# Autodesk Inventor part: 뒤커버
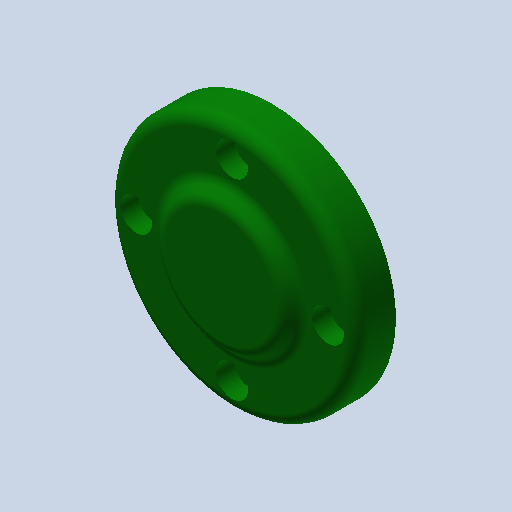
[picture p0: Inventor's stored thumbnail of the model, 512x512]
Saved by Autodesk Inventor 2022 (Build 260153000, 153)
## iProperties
Created: 2015-09
Part Number: 뒤커버
Material: 알루미늄 6061
Document SubType Name: Modeling
Designer: mduedu
Density: 1 g/cm^3
Appearance: 진녹색
Author: mduedu
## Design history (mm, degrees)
sketch "스케치1"
  geometry: L1 (0, 9)-(0, -9); L2 (0, 9)-(15, 9); L3 (15, 9)-(18, 6); L4 (18, 6)-(31, 6); L5 (31, 6)-(31, -4); L6 (31, -4)-(17.5, -4); L7 (17.5, -4)-(17.5, -9); L8 (17.5, -9)-(0, -9); 2 further points
  constraints: 16 end point, 3 parallel, 2 perpendicular, 1 coincident, 1 horizontal, 1 midpoint, 1 vertical
  dimensions: "d1" = 3 distance between parallel lines of L4 L2; "d2" = 10 distance of L4.end L5.end; "d3" = 36 diameter of L3.end L1; "d4" = 35 diameter of L7 L1; "d5" = 62 diameter of L5 L1; "d7" = 45 deg angle of L3 L5; "d48" = 5 distance between parallel lines of L6 L8
revolve "회전1" sketch "스케치1" stored, may be unused: angle "d8" = 90 deg
hole "구멍1" diameter "d11" = 30; stored, may be unused: countersink angle "d15" = 90 deg, drill point angle "d17" = 0 deg; dims "d12" = 6, "d13" = 4, "d14" = 2, "d16" = 10, "d49" = 10, "d50" = 10
fillet "모깎기1" dims "d18" = 3
fillet "모깎기2" dims "d25" = 3
fillet "모깎기3" dims "d26" = 3
sketch "스케치3"
  geometry: 4 further points
hole "구멍2" sketch "스케치3" at (-24, 0), (0, -24), (24, 0), (0, 24) diameter "d35" = 4.5; stored, may be unused: countersink angle "d39" = 90 deg, drill point angle "d41" = 0 deg; dims "d36" = 6, "d37" = 8, "d38" = 4.6, "d40" = 8
chamfer "모따기3" distance "d42" = 1; stored, may be unused: second distance "d43" = 2, angle "d44" = 45 deg
fillet "모깎기4" dims "d45" = 3
node "솔리드1"
sketch "스케치2" dims "d27" = 48
  geometry: 6 further points
  constraints: 2 vertical alignment, 1 coincident, 7 other
  dimensions: "d33" = 360 deg dimension on point (0, 0) point (0, 24) (derived)
